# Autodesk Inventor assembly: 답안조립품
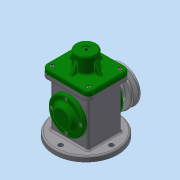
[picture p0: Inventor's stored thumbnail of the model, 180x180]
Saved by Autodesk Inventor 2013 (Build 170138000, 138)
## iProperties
Created: 2018-10
Part Number: 답안조립품
Document SubType Name: Assembly
Designer: Gpr
Author: Gpr
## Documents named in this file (18)
- C:\Users\Administrator\Desktop\481007V1034\답안조립품.iam
- C:\Users\Administrator\Desktop\481007V1034\본체.ipt
- C:\Users\Administrator\Desktop\481007V1034\E-링.ipt
- C:\Users\Administrator\Desktop\481007V1034\V-벨트풀리.ipt
- C:\Users\Administrator\Desktop\481007V1034\덮개.ipt
- C:\Users\Administrator\Desktop\481007V1034\뒤커버.ipt
- C:\Users\Administrator\Desktop\481007V1034\링크.ipt
- C:\Users\Administrator\Desktop\481007V1034\베어링 17 x 40 x 12.ipt
- C:\Users\Administrator\Desktop\481007V1034\볼트 M4 x 8.ipt
- C:\Users\Administrator\Desktop\481007V1034\볼트 M4 x 10.ipt
- C:\Users\Administrator\Desktop\481007V1034\슬라이더.ipt
- C:\Users\Administrator\Desktop\481007V1034\앞커버.ipt
- C:\Users\Administrator\Desktop\481007V1034\오일 실 17 30 8.ipt
- C:\Users\Administrator\Desktop\481007V1034\와셔 4x16.ipt
- C:\Users\Administrator\Desktop\481007V1034\클레비스 핀 6 x 22.ipt
- 클레비스 핀 6 x 22.ipt
- C:\Users\Administrator\Desktop\481007V1034\키 4 x 4 x 12.ipt
- C:\Users\Administrator\Desktop\481007V1034\편심축.ipt
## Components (2 placed, 2 different names)
1. E-링:1
2. V-벨트풀리:1
